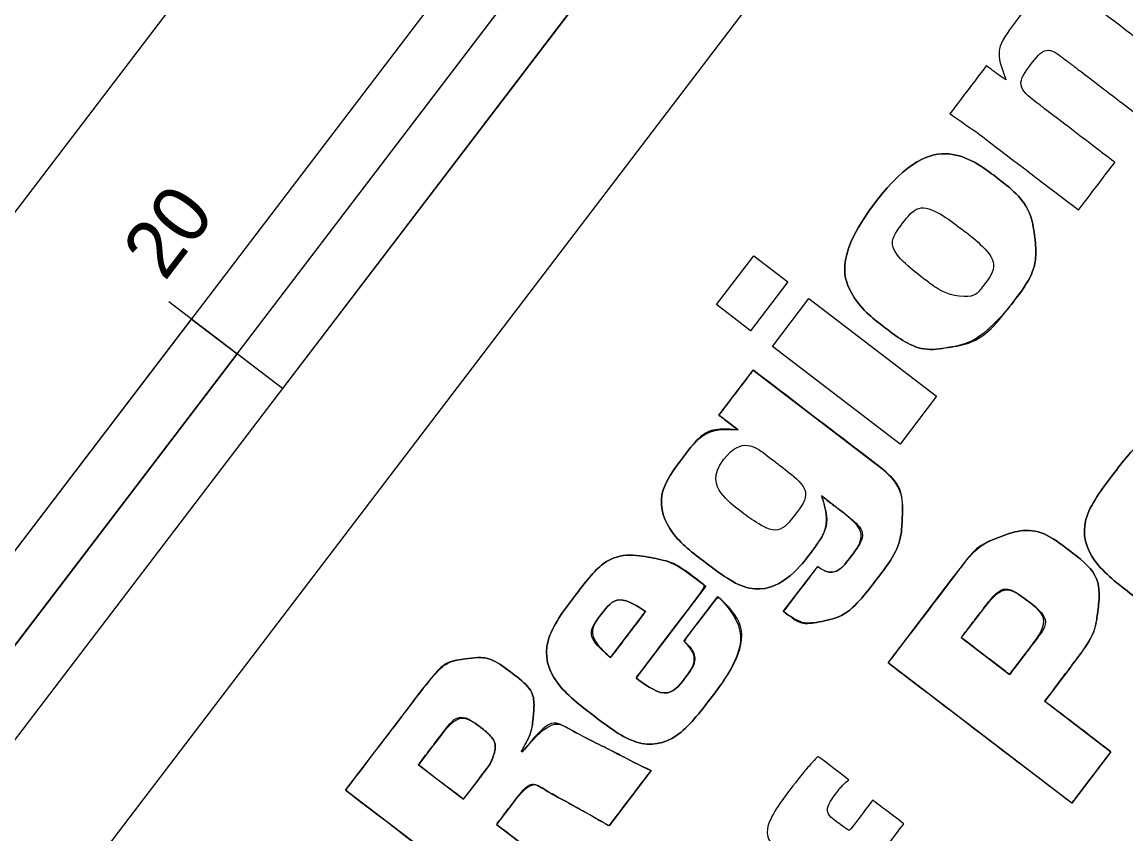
# Model space of a CAD drawing. Extents: x 599744 to 600217, y 4827560 to 4828065.
# Drawn here: x 600147.25 to 600166.53, y 4827888.63 to 4827902.8 of the extents above; entities that cross this region are included whole.
import ezdxf

# ---------------------------------------------------------------- set-up
doc = ezdxf.new("R2010")
doc.units = 0
for name, color, linetype in [('G-ANNO-BAR', 7, 'Continuous'), ('G-TTLB-LOGO', 7, 'Continuous'), ('G-TTLB-OTLN', 7, 'Continuous')]:
    doc.layers.add(name, color=color, linetype=linetype)

msp = doc.modelspace()

# ---------------------------------------------------------------- linework, layer by layer
at = {"layer": 'G-ANNO-BAR'}
for p, q in [((600132.013, 4827873.761), (600156.275, 4827905.563)), ((600132.808, 4827873.154), (600157.07, 4827904.956)), ((600133.603, 4827872.547), (600157.865, 4827904.35)), ((600151.8, 4827896.399), (600149.812, 4827897.915))]:
    msp.add_line(p, q, dxfattribs=at)
for points in [[(600151.004, 4827897.006), (600157.07, 4827904.956), (600157.865, 4827904.35), (600151.8, 4827896.399)], [(600144.144, 4827889.662), (600150.209, 4827897.612), (600151.004, 4827897.006), (600144.939, 4827889.055)]]:
    msp.add_lwpolyline(points, close=True, dxfattribs=at)
at = {"layer": 'G-TTLB-LOGO'}
for p, q in [((600159.38, 4827897.865), (600160.031, 4827898.719)), ((600160.031, 4827898.719), (600160.627, 4827898.264)), ((600160.627, 4827898.264), (600159.975, 4827897.41)), ((600159.975, 4827897.41), (600159.38, 4827897.865)), ((600160.356, 4827897.134), (600160.993, 4827897.97)), ((600160.993, 4827897.97), (600163.225, 4827896.267)), ((600162.588, 4827895.431), (600160.356, 4827897.134)), ((600163.225, 4827896.267), (600162.588, 4827895.431)), ((600161.507, 4827894.301), (600161.214, 4827894.525)), ((600160.547, 4827892.508), (600161.148, 4827893.295)), ((600159.196, 4827892.95), (600157.975, 4827891.349)), ((600158.81, 4827891.992), (600159.404, 4827892.77)), ((600157.528, 4827891.704), (600158.142, 4827892.509)), ((600155.972, 4827890.069), (600155.989, 4827890.056)), ((600158.24, 4827889.732), (600157.504, 4827888.767))]:
    msp.add_line(p, q, dxfattribs=at)
for points in [[(600159.38, 4827897.865), (600160.031, 4827898.719), (600160.627, 4827898.264), (600159.975, 4827897.41), (600159.38, 4827897.865)], [(600160.356, 4827897.134), (600160.993, 4827897.97), (600163.225, 4827896.267), (600162.588, 4827895.431), (600160.356, 4827897.134)], [(600159.758, 4827895.678), (600159.42, 4827895.936), (600160.021, 4827896.723), (600162.101, 4827895.135)], [(600165.551, 4827891.521), (600165.115, 4827890.94), (600166.271, 4827890.058), (600165.589, 4827889.164), (600162.379, 4827891.613), (600163.505, 4827893.089)], [(600163.955, 4827892.444), (600163.656, 4827892.052), (600164.501, 4827891.408), (600164.803, 4827891.804)], [(600155.822, 4827889.163), (600155.537, 4827888.79), (600156.791, 4827887.833), (600156.109, 4827886.939), (600152.899, 4827889.389), (600154.032, 4827890.874)], [(600154.427, 4827890.165), (600154.172, 4827889.831), (600154.959, 4827889.231), (600155.214, 4827889.564)]]:
    msp.add_lwpolyline(points, dxfattribs=at)
for points in [[(600163.948, 4827900.857), (600163.948, 4827900.857), (600163.456, 4827901.198), (600163.456, 4827901.198), (600163.456, 4827901.198), (600164.093, 4827902.034), (600164.093, 4827902.034), (600164.093, 4827902.034), (600164.443, 4827901.781), (600164.443, 4827901.781), (600164.352, 4827902.012), (600164.265, 4827902.36), (600164.618, 4827902.822), (600165.242, 4827903.641), (600165.864, 4827903.166), (600166.171, 4827902.932), (600166.171, 4827902.932), (600167.523, 4827901.9), (600167.523, 4827901.9), (600167.523, 4827901.9), (600166.885, 4827901.065), (600166.885, 4827901.065), (600166.885, 4827901.065), (600165.605, 4827902.041), (600165.605, 4827902.041), (600165.449, 4827902.16), (600165.133, 4827902.401), (600164.872, 4827902.059), (600164.587, 4827901.685), (600164.978, 4827901.387), (600165.059, 4827901.325), (600165.059, 4827901.325), (600166.339, 4827900.349), (600166.339, 4827900.349), (600166.339, 4827900.349), (600165.705, 4827899.517), (600165.705, 4827899.517), (600165.705, 4827899.517), (600163.948, 4827900.857), (600163.948, 4827900.857)], [(600163.948, 4827900.857), (600163.948, 4827900.857), (600163.456, 4827901.198), (600163.456, 4827901.198), (600163.456, 4827901.198), (600164.093, 4827902.034), (600164.093, 4827902.034), (600164.093, 4827902.034), (600164.443, 4827901.781), (600164.443, 4827901.781), (600164.352, 4827902.012), (600164.265, 4827902.36), (600164.618, 4827902.822), (600165.242, 4827903.641), (600165.864, 4827903.166), (600166.171, 4827902.932), (600166.171, 4827902.932), (600167.523, 4827901.9), (600167.523, 4827901.9), (600167.523, 4827901.9), (600166.885, 4827901.065), (600166.885, 4827901.065), (600166.885, 4827901.065), (600165.605, 4827902.041), (600165.605, 4827902.041), (600165.449, 4827902.16), (600165.133, 4827902.401), (600164.872, 4827902.059), (600164.587, 4827901.685), (600164.978, 4827901.387), (600165.059, 4827901.325), (600165.059, 4827901.325), (600166.339, 4827900.349), (600166.339, 4827900.349), (600166.339, 4827900.349), (600165.705, 4827899.517), (600165.705, 4827899.517), (600165.705, 4827899.517), (600163.948, 4827900.857), (600163.948, 4827900.857)], [(600162.16, 4827899.656), (600162.713, 4827900.381), (600163.508, 4827900.667), (600164.3, 4827900.063), (600164.624, 4827899.816), (600164.882, 4827899.471), (600164.937, 4827899.064), (600164.977, 4827898.738), (600164.904, 4827898.357), (600164.555, 4827897.899), (600164.178, 4827897.406), (600163.814, 4827897.177), (600163.439, 4827897.119), (600162.997, 4827897.047), (600162.617, 4827897.239), (600162.345, 4827897.446), (600161.661, 4827897.969), (600161.485, 4827898.771), (600162.16, 4827899.656)], [(600162.16, 4827899.656), (600162.713, 4827900.381), (600163.508, 4827900.667), (600164.3, 4827900.063), (600164.624, 4827899.816), (600164.882, 4827899.471), (600164.937, 4827899.064), (600164.977, 4827898.738), (600164.904, 4827898.357), (600164.555, 4827897.899), (600164.477, 4827897.798), (600164.401, 4827897.707), (600164.324, 4827897.628)], [(600164.324, 4827897.628), (600164.028, 4827897.319), (600163.737, 4827897.165), (600163.439, 4827897.119), (600162.997, 4827897.047), (600162.617, 4827897.239), (600162.345, 4827897.446), (600161.661, 4827897.969), (600161.485, 4827898.771), (600162.16, 4827899.656)], [(600163.622, 4827898.013), (600163.865, 4827897.982), (600163.99, 4827898.126), (600164.047, 4827898.202), (600164.325, 4827898.567), (600163.984, 4827898.94), (600163.673, 4827899.177), (600163.286, 4827899.472), (600162.89, 4827899.626), (600162.636, 4827899.293), (600162.354, 4827898.924), (600162.678, 4827898.564), (600163.011, 4827898.31), (600163.158, 4827898.198), (600163.386, 4827898.045), (600163.622, 4827898.013)], [(600163.622, 4827898.013), (600163.865, 4827897.982), (600163.99, 4827898.126), (600164.047, 4827898.202), (600164.325, 4827898.567), (600163.984, 4827898.94), (600163.673, 4827899.177), (600163.286, 4827899.472), (600162.89, 4827899.626), (600162.636, 4827899.293), (600162.354, 4827898.924), (600162.678, 4827898.564), (600163.011, 4827898.31), (600163.158, 4827898.198), (600163.386, 4827898.045), (600163.622, 4827898.013)], [(600160.021, 4827896.723), (600160.021, 4827896.723), (600162.101, 4827895.135), (600162.101, 4827895.135), (600162.369, 4827894.932), (600162.643, 4827894.637), (600162.626, 4827894.172), (600162.618, 4827893.876), (600162.522, 4827893.52), (600162.173, 4827893.062), (600161.98, 4827892.808), (600161.622, 4827892.413), (600161.201, 4827892.333), (600160.879, 4827892.269), (600160.666, 4827892.424), (600160.547, 4827892.508), (600160.547, 4827892.508), (600161.148, 4827893.295), (600161.148, 4827893.295), (600161.32, 4827893.17), (600161.528, 4827893.202), (600161.711, 4827893.443), (600162.03, 4827893.861), (600161.748, 4827894.118), (600161.507, 4827894.301), (600161.507, 4827894.301), (600161.214, 4827894.525), (600161.214, 4827894.525), (600161.379, 4827894.041), (600161.123, 4827893.659), (600161.025, 4827893.53), (600160.665, 4827893.059), (600159.975, 4827892.762), (600159.161, 4827893.383), (600158.556, 4827893.844), (600158.298, 4827894.548), (600158.817, 4827895.228), (600159.146, 4827895.66), (600159.495, 4827895.702), (600159.758, 4827895.678), (600159.758, 4827895.678), (600159.42, 4827895.936), (600159.42, 4827895.936), (600159.42, 4827895.936), (600160.021, 4827896.723), (600160.021, 4827896.723)], [(600161.214, 4827894.525), (600161.379, 4827894.041), (600161.123, 4827893.659), (600161.025, 4827893.53), (600160.665, 4827893.059), (600159.975, 4827892.762), (600159.161, 4827893.383), (600158.556, 4827893.844), (600158.298, 4827894.548), (600158.817, 4827895.228), (600159.146, 4827895.66), (600159.495, 4827895.702), (600159.758, 4827895.678)], [(600159.508, 4827895.165), (600159.294, 4827894.885), (600159.437, 4827894.537), (600159.81, 4827894.252), (600160.046, 4827894.073), (600160.473, 4827893.831), (600160.755, 4827894.2), (600161.06, 4827894.6), (600160.599, 4827894.973), (600160.439, 4827895.095), (600160.323, 4827895.183), (600159.817, 4827895.57), (600159.508, 4827895.165)], [(600159.508, 4827895.165), (600159.294, 4827894.885), (600159.437, 4827894.537), (600159.81, 4827894.252), (600160.046, 4827894.073), (600160.473, 4827893.831), (600160.755, 4827894.2), (600161.06, 4827894.6), (600160.599, 4827894.973), (600160.439, 4827895.095), (600160.323, 4827895.183), (600159.817, 4827895.57), (600159.508, 4827895.165)], [(600167.373, 4827893.466), (600167.493, 4827893.375), (600167.915, 4827893.052), (600168.241, 4827893.479), (600168.41, 4827893.701), (600168.4, 4827893.928), (600168.208, 4827894.109), (600168.208, 4827894.109), (600168.802, 4827894.887), (600168.802, 4827894.887), (600169.314, 4827894.398), (600169.132, 4827893.707), (600168.691, 4827893.129), (600168.097, 4827892.35), (600167.387, 4827892.231), (600166.649, 4827892.794), (600165.902, 4827893.364), (600165.695, 4827894.099), (600166.323, 4827894.921), (600166.798, 4827895.544), (600167.272, 4827895.639), (600167.703, 4827895.55), (600167.969, 4827895.502), (600168.203, 4827895.365), (600168.594, 4827895.067), (600168.594, 4827895.067), (600167.373, 4827893.466), (600167.373, 4827893.466)], [(600168.802, 4827894.887), (600169.314, 4827894.398), (600169.132, 4827893.707), (600168.691, 4827893.129), (600168.097, 4827892.35), (600167.387, 4827892.231), (600166.649, 4827892.794), (600165.902, 4827893.364), (600165.695, 4827894.099), (600166.323, 4827894.921), (600166.798, 4827895.544), (600167.272, 4827895.639), (600167.703, 4827895.55), (600167.969, 4827895.502), (600168.203, 4827895.365), (600168.594, 4827895.067)], [(600162.101, 4827895.135), (600162.369, 4827894.932), (600162.643, 4827894.637), (600162.626, 4827894.172), (600162.618, 4827893.876), (600162.522, 4827893.52), (600162.173, 4827893.062), (600161.98, 4827892.808), (600161.622, 4827892.413), (600161.201, 4827892.333), (600160.879, 4827892.269), (600160.666, 4827892.424), (600160.547, 4827892.508)], [(600161.148, 4827893.295), (600161.32, 4827893.17), (600161.528, 4827893.202), (600161.711, 4827893.443), (600162.03, 4827893.861), (600161.748, 4827894.118), (600161.507, 4827894.301)], [(600162.379, 4827891.613), (600162.379, 4827891.613), (600163.505, 4827893.089), (600163.505, 4827893.089), (600163.695, 4827893.339), (600163.942, 4827893.663), (600164.307, 4827893.8), (600164.678, 4827893.946), (600165.107, 4827893.908), (600165.524, 4827893.589), (600166.089, 4827893.158), (600166.059, 4827892.611), (600166.031, 4827892.436), (600165.979, 4827892.081), (600165.683, 4827891.695), (600165.551, 4827891.521), (600165.551, 4827891.521), (600165.115, 4827890.94), (600165.115, 4827890.94), (600165.115, 4827890.94), (600166.271, 4827890.058), (600166.271, 4827890.058), (600166.271, 4827890.058), (600165.589, 4827889.164), (600165.589, 4827889.164), (600165.589, 4827889.164), (600162.379, 4827891.613), (600162.379, 4827891.613)], [(600163.505, 4827893.089), (600163.695, 4827893.339), (600163.942, 4827893.663), (600164.307, 4827893.8), (600164.678, 4827893.946), (600165.107, 4827893.908), (600165.524, 4827893.589), (600166.089, 4827893.158), (600166.059, 4827892.611), (600166.031, 4827892.436), (600165.979, 4827892.081), (600165.683, 4827891.695), (600165.551, 4827891.521)], [(600157.975, 4827891.349), (600158.095, 4827891.257), (600158.517, 4827890.935), (600158.843, 4827891.362), (600159.013, 4827891.584), (600159.002, 4827891.81), (600158.81, 4827891.992), (600158.81, 4827891.992), (600159.404, 4827892.77), (600159.404, 4827892.77), (600159.917, 4827892.28), (600159.734, 4827891.589), (600159.293, 4827891.011), (600158.7, 4827890.233), (600157.989, 4827890.114), (600157.251, 4827890.677), (600156.504, 4827891.247), (600156.298, 4827891.981), (600156.925, 4827892.804), (600157.4, 4827893.426), (600157.874, 4827893.522), (600158.305, 4827893.432), (600158.571, 4827893.384), (600158.805, 4827893.248), (600159.196, 4827892.95), (600159.196, 4827892.95), (600157.975, 4827891.349), (600157.975, 4827891.349)], [(600159.404, 4827892.77), (600159.917, 4827892.28), (600159.734, 4827891.589), (600159.293, 4827891.011), (600158.7, 4827890.233), (600157.989, 4827890.114), (600157.251, 4827890.677), (600156.504, 4827891.247), (600156.298, 4827891.981), (600156.925, 4827892.804), (600157.4, 4827893.426), (600157.874, 4827893.522), (600158.305, 4827893.432), (600158.571, 4827893.384), (600158.805, 4827893.248), (600159.196, 4827892.95)], [(600164.501, 4827891.408), (600164.501, 4827891.408), (600164.803, 4827891.804), (600164.803, 4827891.804), (600164.969, 4827892.022), (600165.237, 4827892.373), (600164.806, 4827892.702), (600164.414, 4827893), (600164.151, 4827892.702), (600163.955, 4827892.444), (600163.955, 4827892.444), (600163.656, 4827892.052), (600163.656, 4827892.052), (600163.656, 4827892.052), (600164.501, 4827891.408), (600164.501, 4827891.408)], [(600164.803, 4827891.804), (600164.969, 4827892.022), (600165.237, 4827892.373), (600164.806, 4827892.702), (600164.414, 4827893), (600164.151, 4827892.702), (600163.955, 4827892.444)], [(600158.142, 4827892.509), (600158.007, 4827892.598), (600157.648, 4827892.829), (600157.37, 4827892.465), (600157.092, 4827892.1), (600157.428, 4827891.794), (600157.528, 4827891.704), (600157.528, 4827891.704), (600158.142, 4827892.509), (600158.142, 4827892.509)], [(600158.142, 4827892.509), (600158.007, 4827892.598), (600157.648, 4827892.829), (600157.37, 4827892.465), (600157.092, 4827892.1), (600157.428, 4827891.794), (600157.528, 4827891.704)], [(600157.975, 4827891.349), (600158.095, 4827891.257), (600158.517, 4827890.935), (600158.843, 4827891.362), (600159.013, 4827891.584), (600159.002, 4827891.81), (600158.81, 4827891.992)], [(600152.899, 4827889.389), (600152.899, 4827889.389), (600154.032, 4827890.874), (600154.032, 4827890.874), (600154.473, 4827891.452), (600154.675, 4827891.643), (600155.016, 4827891.685), (600155.189, 4827891.708), (600155.462, 4827891.697), (600155.808, 4827891.432), (600156.16, 4827891.164), (600156.202, 4827890.906), (600156.18, 4827890.684), (600156.153, 4827890.381), (600156.026, 4827890.169), (600155.972, 4827890.069), (600155.972, 4827890.069), (600155.989, 4827890.056), (600155.989, 4827890.056), (600156.482, 4827890.665), (600156.766, 4827890.468), (600157.333, 4827890.185), (600157.581, 4827890.061), (600158.056, 4827889.812), (600158.24, 4827889.732), (600158.24, 4827889.732), (600157.504, 4827888.767), (600157.504, 4827888.767), (600157.378, 4827888.838), (600157.009, 4827889.048), (600156.734, 4827889.199), (600156.305, 4827889.434), (600156.128, 4827889.564), (600155.822, 4827889.163), (600155.822, 4827889.163), (600155.537, 4827888.79), (600155.537, 4827888.79), (600155.537, 4827888.79), (600156.791, 4827887.833), (600156.791, 4827887.833), (600156.791, 4827887.833), (600156.109, 4827886.939), (600156.109, 4827886.939), (600156.109, 4827886.939), (600152.899, 4827889.389), (600152.899, 4827889.389)], [(600154.032, 4827890.874), (600154.473, 4827891.452), (600154.675, 4827891.643), (600155.016, 4827891.685), (600155.189, 4827891.708), (600155.462, 4827891.697), (600155.808, 4827891.432), (600156.16, 4827891.164), (600156.202, 4827890.906), (600156.18, 4827890.684), (600156.153, 4827890.381), (600156.026, 4827890.169), (600155.972, 4827890.069)], [(600154.959, 4827889.231), (600154.959, 4827889.231), (600155.214, 4827889.564), (600155.214, 4827889.564), (600155.363, 4827889.76), (600155.438, 4827889.858), (600155.468, 4827889.954), (600155.556, 4827890.197), (600155.386, 4827890.39), (600155.284, 4827890.468), (600154.888, 4827890.77), (600154.623, 4827890.423), (600154.427, 4827890.165), (600154.427, 4827890.165), (600154.172, 4827889.831), (600154.172, 4827889.831), (600154.172, 4827889.831), (600154.959, 4827889.231), (600154.959, 4827889.231)], [(600155.214, 4827889.564), (600155.363, 4827889.76), (600155.438, 4827889.858), (600155.468, 4827889.954), (600155.556, 4827890.197), (600155.386, 4827890.39), (600155.284, 4827890.468), (600154.888, 4827890.77), (600154.623, 4827890.423), (600154.427, 4827890.165)], [(600155.989, 4827890.056), (600156.482, 4827890.665), (600156.766, 4827890.468), (600157.333, 4827890.185), (600157.581, 4827890.061), (600158.056, 4827889.812), (600158.24, 4827889.732)], [(600161.692, 4827889.569), (600161.656, 4827889.541), (600161.573, 4827889.47), (600161.489, 4827889.359), (600161.227, 4827889.016), (600161.51, 4827888.815), (600161.7, 4827888.677), (600161.7, 4827888.677), (600162.11, 4827889.215), (600162.11, 4827889.215), (600162.11, 4827889.215), (600162.653, 4827888.801), (600162.653, 4827888.801), (600162.653, 4827888.801), (600162.242, 4827888.263), (600162.242, 4827888.263), (600162.242, 4827888.263), (600163.923, 4827886.981), (600163.923, 4827886.981), (600163.923, 4827886.981), (600163.299, 4827886.163), (600163.299, 4827886.163), (600163.299, 4827886.163), (600161.618, 4827887.445), (600161.618, 4827887.445), (600161.618, 4827887.445), (600161.289, 4827887.013), (600161.289, 4827887.013), (600161.289, 4827887.013), (600160.747, 4827887.427), (600160.747, 4827887.427), (600160.747, 4827887.427), (600161.086, 4827887.872), (600161.086, 4827887.872), (600160.542, 4827888.266), (600160.082, 4827888.631), (600160.75, 4827889.507), (600160.923, 4827889.734), (600161.073, 4827889.893), (600161.154, 4827889.98), (600161.154, 4827889.98), (600161.692, 4827889.569), (600161.692, 4827889.569)], [(600161.692, 4827889.569), (600161.656, 4827889.541), (600161.573, 4827889.47), (600161.489, 4827889.359), (600161.227, 4827889.016), (600161.51, 4827888.815), (600161.7, 4827888.677), (600161.7, 4827888.677), (600162.11, 4827889.215), (600162.11, 4827889.215), (600162.11, 4827889.215), (600162.653, 4827888.801), (600162.653, 4827888.801), (600162.653, 4827888.801), (600162.242, 4827888.263), (600162.242, 4827888.263), (600162.242, 4827888.263), (600163.923, 4827886.981), (600163.923, 4827886.981), (600163.923, 4827886.981), (600163.299, 4827886.163), (600163.299, 4827886.163), (600163.299, 4827886.163), (600161.618, 4827887.445), (600161.618, 4827887.445), (600161.618, 4827887.445), (600161.289, 4827887.013), (600161.289, 4827887.013), (600161.289, 4827887.013), (600160.747, 4827887.427), (600160.747, 4827887.427), (600160.747, 4827887.427), (600161.086, 4827887.872), (600161.086, 4827887.872), (600160.542, 4827888.266), (600160.082, 4827888.631), (600160.75, 4827889.507), (600160.923, 4827889.734), (600161.073, 4827889.893), (600161.154, 4827889.98), (600161.154, 4827889.98), (600161.692, 4827889.569), (600161.692, 4827889.569)], [(600157.504, 4827888.767), (600157.378, 4827888.838), (600157.009, 4827889.048), (600156.734, 4827889.199), (600156.305, 4827889.434), (600156.128, 4827889.564), (600155.822, 4827889.163)]]:
    msp.add_open_spline(points, degree=3, dxfattribs=at)
at = {"layer": 'G-TTLB-OTLN'}
for p, q in [((600166.482, 4827924.86), (600128.027, 4827874.452)), ((600172.843, 4827920.007), (600134.387, 4827869.6))]:
    msp.add_line(p, q, dxfattribs=at)

# ---------------------------------------------------------------- texts
at = {"layer": 'G-ANNO-BAR'}
msp.add_text('20', height=1, rotation=52.6603, dxfattribs=at).set_placement((600149.74, 4827898.255))

doc.saveas('drawing.dxf')
